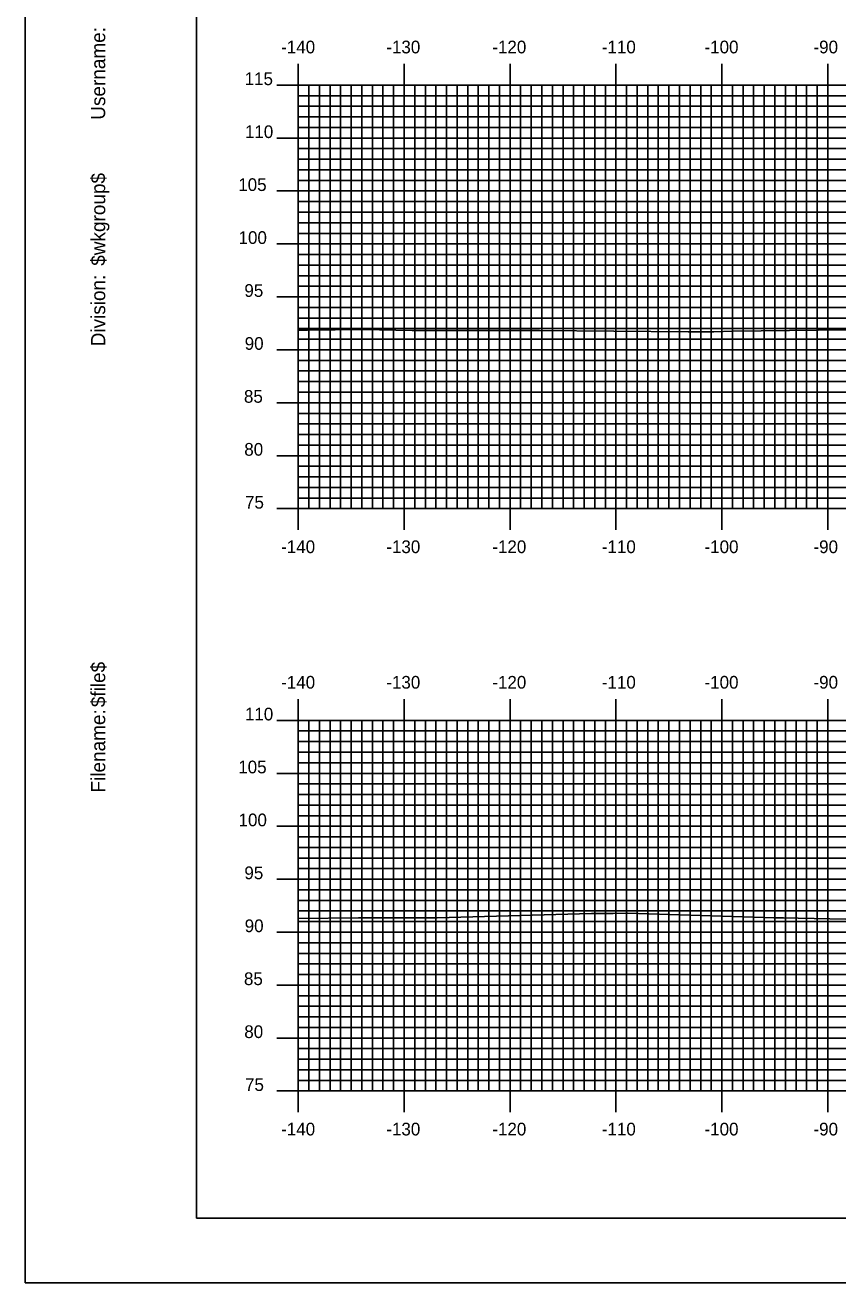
# Model space of a CAD drawing. Extents: x 854903 to 855247, y 364366 to 364586.
# Drawn here: x 854903.5 to 854980.2, y 364365.7 to 364484.5 of the extents above; entities that cross this region are included whole.
import ezdxf

# ---------------------------------------------------------------- set-up
doc = ezdxf.new("R2010")
doc.units = 0
for name, color, linetype in [('BORDER', 7, 'Continuous'), ('H_V ANNOTATION', 7, 'Continuous'), ('MAJOR', 7, 'Continuous'), ('MINOR', 7, 'Continuous'), ('PLOT BOUNDARY', 7, 'Continuous'), ('S_Roadway_Centerline', 7, 'Continuous')]:
    doc.layers.add(name, color=color, linetype=linetype)

msp = doc.modelspace()

# ---------------------------------------------------------------- linework, layer by layer
at = {"layer": 'BORDER'}
msp.add_lwpolyline([(854919.66, 364371.79), (855239.66, 364371.79), (855239.66, 364581.79), (854919.66, 364581.79)], close=True, dxfattribs=at)
at = {"layer": 'MAJOR'}
for p, q in [((854929.26, 364480.79), (854929.26, 364478.79)), ((854939.26, 364480.79), (854939.26, 364478.79)), ((854949.26, 364480.79), (854949.26, 364478.79)), ((854959.26, 364480.79), (854959.26, 364478.79)), ((854969.26, 364480.79), (854969.26, 364478.79)), ((854979.26, 364480.79), (854979.26, 364478.79)), ((854927.25, 364478.79), (854929.26, 364478.79)), ((854929.26, 364478.79), (855209.26, 364478.79)), ((854929.26, 364438.79), (854929.26, 364478.79)), ((854929.26, 364438.79), (854929.26, 364478.79)), ((854929.26, 364478.79), (855209.26, 364478.79)), ((854939.26, 364438.79), (854939.26, 364478.79)), ((854949.26, 364438.79), (854949.26, 364478.79)), ((854959.26, 364438.79), (854959.26, 364478.79)), ((854969.26, 364438.79), (854969.26, 364478.79)), ((854979.26, 364438.79), (854979.26, 364478.79)), ((854927.25, 364473.79), (854929.26, 364473.79)), ((854929.26, 364473.79), (855209.26, 364473.79)), ((854927.25, 364468.79), (854929.26, 364468.79)), ((854929.26, 364468.79), (855209.26, 364468.79)), ((854927.25, 364463.79), (854929.26, 364463.79)), ((854929.26, 364463.79), (855209.26, 364463.79)), ((854927.25, 364458.79), (854929.26, 364458.79)), ((854929.26, 364458.79), (855209.26, 364458.79)), ((854927.25, 364453.79), (854929.26, 364453.79)), ((854929.26, 364453.79), (855209.26, 364453.79)), ((854927.25, 364448.79), (854929.26, 364448.79)), ((854929.26, 364448.79), (855209.26, 364448.79)), ((854927.25, 364443.79), (854929.26, 364443.79)), ((854929.26, 364443.79), (855209.26, 364443.79)), ((854927.25, 364438.79), (854929.26, 364438.79)), ((854929.26, 364438.79), (855209.26, 364438.79)), ((854929.26, 364438.79), (855209.26, 364438.79)), ((854929.26, 364436.78), (854929.26, 364438.79)), ((854939.26, 364436.78), (854939.26, 364438.79)), ((854949.26, 364436.78), (854949.26, 364438.79)), ((854959.26, 364436.78), (854959.26, 364438.79)), ((854969.26, 364436.78), (854969.26, 364438.79)), ((854979.26, 364436.78), (854979.26, 364438.79)), ((854929.26, 364420.79), (854929.26, 364418.79)), ((854939.26, 364420.79), (854939.26, 364418.79)), ((854949.26, 364420.79), (854949.26, 364418.79)), ((854959.26, 364420.79), (854959.26, 364418.79)), ((854969.26, 364420.79), (854969.26, 364418.79)), ((854979.26, 364420.79), (854979.26, 364418.79)), ((854927.25, 364418.79), (854929.26, 364418.79)), ((854929.26, 364418.79), (855209.26, 364418.79)), ((854929.26, 364383.79), (854929.26, 364418.79)), ((854929.26, 364383.79), (854929.26, 364418.79)), ((854929.26, 364418.79), (855209.26, 364418.79)), ((854939.26, 364383.79), (854939.26, 364418.79)), ((854949.26, 364383.79), (854949.26, 364418.79)), ((854959.26, 364383.79), (854959.26, 364418.79)), ((854969.26, 364383.79), (854969.26, 364418.79)), ((854979.26, 364383.79), (854979.26, 364418.79)), ((854927.25, 364413.79), (854929.26, 364413.79)), ((854929.26, 364413.79), (855209.26, 364413.79)), ((854927.25, 364408.79), (854929.26, 364408.79)), ((854929.26, 364408.79), (855209.26, 364408.79)), ((854927.25, 364403.79), (854929.26, 364403.79)), ((854929.26, 364403.79), (855209.26, 364403.79)), ((854927.25, 364398.79), (854929.26, 364398.79)), ((854929.26, 364398.79), (855209.26, 364398.79)), ((854927.25, 364393.79), (854929.26, 364393.79)), ((854929.26, 364393.79), (855209.26, 364393.79)), ((854927.25, 364388.79), (854929.26, 364388.79)), ((854929.26, 364388.79), (855209.26, 364388.79)), ((854927.25, 364383.79), (854929.26, 364383.79)), ((854929.26, 364383.79), (855209.26, 364383.79)), ((854929.26, 364383.79), (855209.26, 364383.79)), ((854929.26, 364381.78), (854929.26, 364383.79)), ((854939.26, 364381.78), (854939.26, 364383.79)), ((854949.26, 364381.78), (854949.26, 364383.79)), ((854959.26, 364381.78), (854959.26, 364383.79)), ((854969.26, 364381.78), (854969.26, 364383.79)), ((854979.26, 364381.78), (854979.26, 364383.79))]:
    msp.add_line(p, q, dxfattribs=at)
at = {"layer": 'MINOR'}
for p, q in [((854930.26, 364438.79), (854930.26, 364478.79)), ((854931.26, 364438.79), (854931.26, 364478.79)), ((854932.26, 364438.79), (854932.26, 364478.79)), ((854933.26, 364438.79), (854933.26, 364478.79)), ((854934.26, 364438.79), (854934.26, 364478.79)), ((854935.26, 364438.79), (854935.26, 364478.79)), ((854936.26, 364438.79), (854936.26, 364478.79)), ((854937.26, 364438.79), (854937.26, 364478.79)), ((854938.26, 364438.79), (854938.26, 364478.79)), ((854940.26, 364438.79), (854940.26, 364478.79)), ((854941.26, 364438.79), (854941.26, 364478.79)), ((854942.26, 364438.79), (854942.26, 364478.79)), ((854943.26, 364438.79), (854943.26, 364478.79)), ((854944.26, 364438.79), (854944.26, 364478.79)), ((854945.26, 364438.79), (854945.26, 364478.79)), ((854946.26, 364438.79), (854946.26, 364478.79)), ((854947.26, 364438.79), (854947.26, 364478.79)), ((854948.26, 364438.79), (854948.26, 364478.79)), ((854950.26, 364438.79), (854950.26, 364478.79)), ((854951.26, 364438.79), (854951.26, 364478.79)), ((854952.26, 364438.79), (854952.26, 364478.79)), ((854953.26, 364438.79), (854953.26, 364478.79)), ((854954.26, 364438.79), (854954.26, 364478.79)), ((854955.26, 364438.79), (854955.26, 364478.79)), ((854956.26, 364438.79), (854956.26, 364478.79)), ((854957.26, 364438.79), (854957.26, 364478.79)), ((854958.26, 364438.79), (854958.26, 364478.79)), ((854960.26, 364438.79), (854960.26, 364478.79)), ((854961.26, 364438.79), (854961.26, 364478.79)), ((854962.26, 364438.79), (854962.26, 364478.79)), ((854963.26, 364438.79), (854963.26, 364478.79)), ((854964.26, 364438.79), (854964.26, 364478.79)), ((854965.26, 364438.79), (854965.26, 364478.79)), ((854966.26, 364438.79), (854966.26, 364478.79)), ((854967.26, 364438.79), (854967.26, 364478.79)), ((854968.26, 364438.79), (854968.26, 364478.79)), ((854970.26, 364438.79), (854970.26, 364478.79)), ((854971.26, 364438.79), (854971.26, 364478.79)), ((854972.26, 364438.79), (854972.26, 364478.79)), ((854973.26, 364438.79), (854973.26, 364478.79)), ((854974.26, 364438.79), (854974.26, 364478.79)), ((854975.26, 364438.79), (854975.26, 364478.79)), ((854976.26, 364438.79), (854976.26, 364478.79)), ((854977.26, 364438.79), (854977.26, 364478.79)), ((854978.26, 364438.79), (854978.26, 364478.79)), ((854929.26, 364477.79), (855209.26, 364477.79)), ((854929.26, 364477.79), (854931.26, 364477.79)), ((854929.26, 364476.79), (855209.26, 364476.79)), ((854929.26, 364476.79), (854931.26, 364476.79)), ((854929.26, 364475.79), (855209.26, 364475.79)), ((854929.26, 364475.79), (854931.26, 364475.79)), ((854929.26, 364474.79), (855209.26, 364474.79)), ((854929.26, 364474.79), (854931.26, 364474.79)), ((854929.26, 364472.79), (855209.26, 364472.79)), ((854929.26, 364472.79), (854931.26, 364472.79)), ((854929.26, 364471.79), (855209.26, 364471.79)), ((854929.26, 364471.79), (854931.26, 364471.79)), ((854929.26, 364470.79), (855209.26, 364470.79)), ((854929.26, 364470.79), (854931.26, 364470.79)), ((854929.26, 364469.79), (855209.26, 364469.79)), ((854929.26, 364469.79), (854931.26, 364469.79)), ((854929.26, 364467.79), (855209.26, 364467.79)), ((854929.26, 364467.79), (854931.26, 364467.79)), ((854929.26, 364466.79), (855209.26, 364466.79)), ((854929.26, 364466.79), (854931.26, 364466.79)), ((854929.26, 364465.79), (855209.26, 364465.79)), ((854929.26, 364465.79), (854931.26, 364465.79)), ((854929.26, 364464.79), (855209.26, 364464.79)), ((854929.26, 364464.79), (854931.26, 364464.79)), ((854929.26, 364462.79), (855209.26, 364462.79)), ((854929.26, 364462.79), (854931.26, 364462.79)), ((854929.26, 364461.79), (855209.26, 364461.79)), ((854929.26, 364461.79), (854931.26, 364461.79)), ((854929.26, 364460.79), (855209.26, 364460.79)), ((854929.26, 364460.79), (854931.26, 364460.79)), ((854929.26, 364459.79), (855209.26, 364459.79)), ((854929.26, 364459.79), (854931.26, 364459.79)), ((854929.26, 364457.79), (855209.26, 364457.79)), ((854929.26, 364457.79), (854931.26, 364457.79)), ((854929.26, 364456.79), (855209.26, 364456.79)), ((854929.26, 364456.79), (854931.26, 364456.79)), ((854929.26, 364455.79), (855209.26, 364455.79)), ((854929.26, 364455.79), (854931.26, 364455.79)), ((854929.26, 364454.79), (855209.26, 364454.79)), ((854929.26, 364454.79), (854931.26, 364454.79)), ((854929.26, 364452.79), (855209.26, 364452.79)), ((854929.26, 364452.79), (854931.26, 364452.79)), ((854929.26, 364451.79), (855209.26, 364451.79)), ((854929.26, 364451.79), (854931.26, 364451.79)), ((854929.26, 364450.79), (855209.26, 364450.79)), ((854929.26, 364450.79), (854931.26, 364450.79)), ((854929.26, 364449.79), (855209.26, 364449.79)), ((854929.26, 364449.79), (854931.26, 364449.79)), ((854929.26, 364447.79), (855209.26, 364447.79)), ((854929.26, 364447.79), (854931.26, 364447.79)), ((854929.26, 364446.79), (855209.26, 364446.79)), ((854929.26, 364446.79), (854931.26, 364446.79)), ((854929.26, 364445.79), (855209.26, 364445.79)), ((854929.26, 364445.79), (854931.26, 364445.79)), ((854929.26, 364444.79), (855209.26, 364444.79)), ((854929.26, 364444.79), (854931.26, 364444.79)), ((854929.26, 364442.79), (855209.26, 364442.79)), ((854929.26, 364442.79), (854931.26, 364442.79)), ((854929.26, 364441.79), (855209.26, 364441.79)), ((854929.26, 364441.79), (854931.26, 364441.79)), ((854929.26, 364440.79), (855209.26, 364440.79)), ((854929.26, 364440.79), (854931.26, 364440.79)), ((854929.26, 364439.79), (855209.26, 364439.79)), ((854929.26, 364439.79), (854931.26, 364439.79)), ((854929.26, 364417.79), (855209.26, 364417.79)), ((854929.26, 364417.79), (854931.26, 364417.79)), ((854930.26, 364383.79), (854930.26, 364418.79)), ((854931.26, 364383.79), (854931.26, 364418.79)), ((854932.26, 364383.79), (854932.26, 364418.79)), ((854933.26, 364383.79), (854933.26, 364418.79)), ((854934.26, 364383.79), (854934.26, 364418.79)), ((854935.26, 364383.79), (854935.26, 364418.79)), ((854936.26, 364383.79), (854936.26, 364418.79)), ((854937.26, 364383.79), (854937.26, 364418.79)), ((854938.26, 364383.79), (854938.26, 364418.79)), ((854940.26, 364383.79), (854940.26, 364418.79)), ((854941.26, 364383.79), (854941.26, 364418.79)), ((854942.26, 364383.79), (854942.26, 364418.79)), ((854943.26, 364383.79), (854943.26, 364418.79)), ((854944.26, 364383.79), (854944.26, 364418.79)), ((854945.26, 364383.79), (854945.26, 364418.79)), ((854946.26, 364383.79), (854946.26, 364418.79)), ((854947.26, 364383.79), (854947.26, 364418.79)), ((854948.26, 364383.79), (854948.26, 364418.79)), ((854950.26, 364383.79), (854950.26, 364418.79)), ((854951.26, 364383.79), (854951.26, 364418.79)), ((854952.26, 364383.79), (854952.26, 364418.79)), ((854953.26, 364383.79), (854953.26, 364418.79)), ((854954.26, 364383.79), (854954.26, 364418.79)), ((854955.26, 364383.79), (854955.26, 364418.79)), ((854956.26, 364383.79), (854956.26, 364418.79)), ((854957.26, 364383.79), (854957.26, 364418.79)), ((854958.26, 364383.79), (854958.26, 364418.79)), ((854960.26, 364383.79), (854960.26, 364418.79)), ((854961.26, 364383.79), (854961.26, 364418.79)), ((854962.26, 364383.79), (854962.26, 364418.79)), ((854963.26, 364383.79), (854963.26, 364418.79)), ((854964.26, 364383.79), (854964.26, 364418.79)), ((854965.26, 364383.79), (854965.26, 364418.79)), ((854966.26, 364383.79), (854966.26, 364418.79)), ((854967.26, 364383.79), (854967.26, 364418.79)), ((854968.26, 364383.79), (854968.26, 364418.79)), ((854970.26, 364383.79), (854970.26, 364418.79)), ((854971.26, 364383.79), (854971.26, 364418.79)), ((854972.26, 364383.79), (854972.26, 364418.79)), ((854973.26, 364383.79), (854973.26, 364418.79)), ((854974.26, 364383.79), (854974.26, 364418.79)), ((854975.26, 364383.79), (854975.26, 364418.79)), ((854976.26, 364383.79), (854976.26, 364418.79)), ((854977.26, 364383.79), (854977.26, 364418.79)), ((854978.26, 364383.79), (854978.26, 364418.79)), ((854929.26, 364416.79), (855209.26, 364416.79)), ((854929.26, 364416.79), (854931.26, 364416.79)), ((854929.26, 364415.79), (855209.26, 364415.79)), ((854929.26, 364415.79), (854931.26, 364415.79)), ((854929.26, 364414.79), (855209.26, 364414.79)), ((854929.26, 364414.79), (854931.26, 364414.79)), ((854929.26, 364412.79), (855209.26, 364412.79)), ((854929.26, 364412.79), (854931.26, 364412.79)), ((854929.26, 364411.79), (855209.26, 364411.79)), ((854929.26, 364411.79), (854931.26, 364411.79)), ((854929.26, 364410.79), (855209.26, 364410.79)), ((854929.26, 364410.79), (854931.26, 364410.79)), ((854929.26, 364409.79), (855209.26, 364409.79)), ((854929.26, 364409.79), (854931.26, 364409.79)), ((854929.26, 364407.79), (855209.26, 364407.79)), ((854929.26, 364407.79), (854931.26, 364407.79)), ((854929.26, 364406.79), (855209.26, 364406.79)), ((854929.26, 364406.79), (854931.26, 364406.79)), ((854929.26, 364405.79), (855209.26, 364405.79)), ((854929.26, 364405.79), (854931.26, 364405.79)), ((854929.26, 364404.79), (855209.26, 364404.79)), ((854929.26, 364404.79), (854931.26, 364404.79)), ((854929.26, 364402.79), (855209.26, 364402.79)), ((854929.26, 364402.79), (854931.26, 364402.79)), ((854929.26, 364401.79), (855209.26, 364401.79)), ((854929.26, 364401.79), (854931.26, 364401.79)), ((854929.26, 364400.79), (855209.26, 364400.79)), ((854929.26, 364400.79), (854931.26, 364400.79)), ((854929.26, 364399.79), (855209.26, 364399.79)), ((854929.26, 364399.79), (854931.26, 364399.79)), ((854929.26, 364397.79), (855209.26, 364397.79)), ((854929.26, 364397.79), (854931.26, 364397.79)), ((854929.26, 364396.79), (855209.26, 364396.79)), ((854929.26, 364396.79), (854931.26, 364396.79)), ((854929.26, 364395.79), (855209.26, 364395.79)), ((854929.26, 364395.79), (854931.26, 364395.79)), ((854929.26, 364394.79), (855209.26, 364394.79)), ((854929.26, 364394.79), (854931.26, 364394.79)), ((854929.26, 364392.79), (855209.26, 364392.79)), ((854929.26, 364392.79), (854931.26, 364392.79)), ((854929.26, 364391.79), (855209.26, 364391.79)), ((854929.26, 364391.79), (854931.26, 364391.79)), ((854929.26, 364390.79), (855209.26, 364390.79)), ((854929.26, 364390.79), (854931.26, 364390.79)), ((854929.26, 364389.79), (855209.26, 364389.79)), ((854929.26, 364389.79), (854931.26, 364389.79)), ((854929.26, 364387.79), (855209.26, 364387.79)), ((854929.26, 364387.79), (854931.26, 364387.79)), ((854929.26, 364386.79), (855209.26, 364386.79)), ((854929.26, 364386.79), (854931.26, 364386.79)), ((854929.26, 364385.79), (855209.26, 364385.79)), ((854929.26, 364385.79), (854931.26, 364385.79)), ((854929.26, 364384.79), (855209.26, 364384.79)), ((854929.26, 364384.79), (854931.26, 364384.79))]:
    msp.add_line(p, q, dxfattribs=at)
at = {"layer": 'PLOT BOUNDARY'}
msp.add_lwpolyline([(854903.47, 364365.67), (855243.47, 364365.67), (855243.47, 364585.67), (854903.47, 364585.67)], close=True, dxfattribs=at)
at = {"layer": 'S_Roadway_Centerline'}
for points in [[(854929.26, 364455.65), (854930.12, 364455.64), (854935.39, 364455.7), (854940.01, 364455.61), (854952.05, 364455.61), (854966.09, 364455.5), (854968.49, 364455.49), (854970.28, 364455.56), (854983.7, 364455.72), (854984.67, 364455.69), (854985.69, 364455.67), (855001.36, 364454.71), (855001.44, 364454.71), (855017.22, 364454.55), (855017.35, 364454.55), (855018.41, 364454.54), (855034.27, 364454.44), (855036.5, 364454.42), (855049.55, 364454.18), (855062.67, 364454.82)], [(854929.26, 364400.09), (854934.94, 364400.14), (854942.39, 364400.15), (854956.95, 364400.54), (854959.01, 364400.56), (854960.38, 364400.58), (854968.31, 364400.32), (854974.18, 364400.14), (854975.07, 364400.15), (854976.45, 364400.12), (854992.99, 364399.77), (855003.15, 364399.71), (855009.46, 364399.41), (855019.32, 364399.48), (855026.25, 364399.61), (855030.09, 364399.38), (855043.99, 364399.28), (855048.97, 364399.15), (855058.3, 364398.86)]]:
    msp.add_lwpolyline(points, dxfattribs=at)

# ---------------------------------------------------------------- texts
at = {"layer": 'BORDER'}
for s, p in [('Username:', (854911.03, 364475.52)), ('$wkgroup$', (854911.03, 364461.73)), ('Division:', (854911.03, 364454.12)), ('$file$', (854911.03, 364420.04)), ('Filename:', (854911.03, 364411.98))]:
    msp.add_text(s, height=1.339, rotation=90, dxfattribs=at).set_placement(p)
at = {"layer": 'H_V ANNOTATION'}
for s, p in [('-140', (854927.64, 364481.79)), ('-130', (854937.57, 364481.79)), ('-120', (854947.58, 364481.79)), ('-110', (854957.92, 364481.79)), ('-100', (854967.62, 364481.79)), ('-90', (854977.91, 364481.79)), ('115', (854924.19, 364478.79)), ('110', (854924.22, 364473.79)), ('105', (854923.59, 364468.79)), ('100', (854923.62, 364463.79)), ('95', (854924.17, 364458.79)), ('90', (854924.2, 364453.79)), ('85', (854924.13, 364448.79)), ('80', (854924.16, 364443.79)), ('75', (854924.23, 364438.79)), ('-140', (854927.64, 364434.59)), ('-130', (854937.57, 364434.59)), ('-120', (854947.58, 364434.59)), ('-110', (854957.92, 364434.59)), ('-100', (854967.62, 364434.59)), ('-90', (854977.91, 364434.59)), ('-140', (854927.64, 364421.79)), ('-130', (854937.57, 364421.79)), ('-120', (854947.58, 364421.79)), ('-110', (854957.92, 364421.79)), ('-100', (854967.62, 364421.79)), ('-90', (854977.91, 364421.79)), ('110', (854924.22, 364418.79)), ('105', (854923.59, 364413.79)), ('100', (854923.62, 364408.79)), ('95', (854924.17, 364403.79)), ('90', (854924.2, 364398.79)), ('85', (854924.13, 364393.79)), ('80', (854924.16, 364388.79)), ('75', (854924.23, 364383.79)), ('-140', (854927.64, 364379.59)), ('-130', (854937.57, 364379.59)), ('-120', (854947.58, 364379.59)), ('-110', (854957.92, 364379.59)), ('-100', (854967.62, 364379.59)), ('-90', (854977.91, 364379.59))]:
    msp.add_text(s, height=1.2, dxfattribs=at).set_placement(p)
at = {"layer": 'MAJOR'}
for p in [(854929.25, 364438.79), (854929.25, 364383.79)]:
    msp.add_text('-', height=0.012, dxfattribs=at).set_placement(p)

doc.saveas('drawing.dxf')
